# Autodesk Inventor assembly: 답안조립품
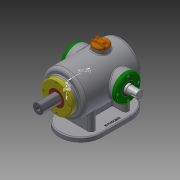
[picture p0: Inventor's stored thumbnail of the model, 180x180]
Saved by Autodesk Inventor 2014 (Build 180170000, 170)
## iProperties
Created: 2017-01
Part Number: 답안조립품
Document SubType Name: Assembly
Designer: user
Mass: 8320.25 g
Surface Area: 4199.47 cm^2
Volume: 2045.98 cm^3
Density: 4.06664 g/cm^3
Author: user
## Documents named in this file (16)
- C:\Users\user\Desktop\370108V1008\답안조립품.iam
- C:\Users\user\Desktop\370108V1008\본체.ipt
- C:\Users\user\Desktop\370108V1008\플레이트.ipt
- C:\Users\user\Desktop\370108V1008\베어링 6205.ipt
- 베어링 6205.ipt
- C:\Users\user\Desktop\370108V1008\축 커버-1.ipt
- C:\Users\user\Desktop\370108V1008\축 커버-2.ipt
- C:\Users\user\Desktop\370108V1008\오일실.ipt
- 오일실.ipt
- C:\Users\user\Desktop\370108V1008\슬라이드 커버.ipt
- C:\Users\user\Desktop\370108V1008\부시.ipt
- C:\Users\user\Desktop\370108V1008\편심축.ipt
- C:\Users\user\Desktop\370108V1008\슬라이드.ipt
- C:\Users\user\Desktop\370108V1008\볼트 M4x0.7.ipt
- C:\Users\user\Desktop\370108V1008\상부 캡.ipt
- C:\Users\user\Desktop\370108V1008\가변스프링.ipt
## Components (14 placed, 3 different names)
1. 플레이트:1 — Insert:1, Insert:2
2. 가변스프링:1 — Mate:3, Mate:4, Mate:6
3. M4x0.7:3 — Insert:12
4. M4x0.7:4
5. M4x0.7:5
6. M4x0.7:6
7. M4x0.7:2 — Insert:13
8. M4x0.7:7
9. M4x0.7:8
10. M4x0.7:9
11. M4x0.7:1 — Insert:14
12. M4x0.7:10
13. M4x0.7:11
14. M4x0.7:12
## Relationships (8: Insert 5, Mate 3)
- Insert:1: 플레이트:1
- Insert:2: 플레이트:1
- Mate:3: 가변스프링:1
- Mate:4: 가변스프링:1
- Mate:6: 가변스프링:1
- Insert:12: M4x0.7:3
- Insert:13: M4x0.7:2
- Insert:14: M4x0.7:1
